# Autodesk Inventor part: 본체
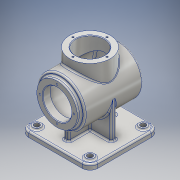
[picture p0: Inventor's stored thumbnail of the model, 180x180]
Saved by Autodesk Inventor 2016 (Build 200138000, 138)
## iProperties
Created: 2015-07
Part Number: 본체
Material: 알루미늄 6061
Document SubType Name: Modeling
Designer: Administrator
Density: 2.7 g/cm^3
Appearance: 알루미늄 - 평지
Mass: 1272.8 g
Surface Area: 1268 cm^2
Volume: 471.408 cm^3
Author: Administrator
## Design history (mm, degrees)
sketch "스케치1"
  geometry: L1 (-65, 65)-(65, 65); L2 (65, 65)-(65, -65); L3 (65, -65)-(-65, -65); L4 (-65, -65)-(-65, 65); 3 further points
  constraints: 8 end point, 2 midpoint, 2 parallel, 2 perpendicular, 1 horizontal, 1 horizontal alignment, 1 vertical alignment
  dimensions: "d0" = 130 distance of L1.start L1.end
extrude "돌출1" new body sketch "스케치1" distance "d1" = 10; taper "d2" = 0 deg
fillet "모깎기1" dims "d3" = 15
sketch "스케치2"
  geometry: C1 r 7.5 at (-50, 50); C2 r 7.5 at (50, 50); C3 r 7.5 at (-50, -50); C4 r 7.5 at (50, -50); A1 r 15 centre (-50, -50) between (-65, -50) and (-50, -65) reference; A2 r 15 centre (-50, 50) between (-50, 65) and (-65, 50) reference; A3 r 15 centre (50, 50) between (65, 50) and (50, 65) reference; A4 r 15 centre (50, -50) between (50, -65) and (65, -50) reference; 5 further points
  constraints: 8 coincident, 4 centre point
  dimensions: "d4" = 15 diameter of C1; "d5" = 15 diameter of C2; "d6" = 15 diameter of C3; "d7" = 15 diameter of C4
extrude "돌출2" join sketch "스케치2" distance "d8" = 3; taper "d9" = 0 deg
sketch "스케치4"
  geometry: C1 r 7.5 at (0, 100) reference; C2 r 7.5 at (0, 0) reference; C3 r 7.5 at (100, 0) reference; C4 r 7.5 at (100, 100) reference; 5 further points
  constraints: 4 coincident
hole "구멍1" sketch "스케치4" at (0, 100), (0, 0), (100, 0), (100, 100) diameter "d10" = 10; stored, may be unused: countersink angle "d14" = 90 deg, drill point angle "d16" = 118 deg; dims "d11" = 6, "d12" = 4, "d13" = 2, "d15" = 8
sketch "스케치6"
  geometry: L1 (-5, 45)-(5, 45); L2 (5, -45)-(-5, -45); L3 (45, 5)-(45, -5); L4 (-45, -5)-(-45, 5); L5 (-5, -45)-(-5, -5); L6 (-5, 5)-(-5, 45); L7 (-45, 5)-(-5, 5); L8 (5, 5)-(45, 5); L9 (5, 45)-(5, 5); L10 (5, -5)-(5, -45); L11 (45, -5)-(5, -5); L12 (-5, -5)-(-45, -5); 3 further points
  constraints: 24 end point, 10 parallel, 6 equal length, 4 perpendicular, 3 horizontal, 2 midpoint, 1 horizontal alignment, 1 vertical alignment
  dimensions: "d17" = 10 distance of L1.start L1.end; "d18" = 90 distance between parallel lines of L2 L1; "d19" = 90 distance between parallel lines of L3 L4; "d20" = 10 distance of L4.start L4.end
extrude "돌출3" join sketch "스케치6" distance "d21" = 68; taper "d22" = 0 deg
sketch "스케치7"
  geometry: C1 r 45 at (0, 78); 1 further point
  constraints: 1 centre point, 1 vertical alignment
  dimensions: "d23" = 90 diameter of C1; "d24" = 78 distance of point (0, 0) C1.centre
extrude "돌출4" join sketch "스케치7" stored distance "d25" = 110; taper "d26" = 0 deg
sketch "스케치9"
  geometry: C1 r 45 at (0, 0) reference; C2 r 38 at (0, 0); 1 further point
  constraints: 1 centre point, 1 coincident
  dimensions: "d27" = 76 diameter of C2
extrude "돌출5" join sketch "스케치9" distance "d28" = 7; taper "d29" = 0 deg
sketch "스케치10"
  geometry: L1 (0, 0)-(0, 140); L2 (0, 140)-(38, 140); L3 (38, 140)-(38, 95); L4 (38, 95)-(0, 95)
  constraints: 8 end point, 2 perpendicular, 1 horizontal, 1 point on line
  dimensions: "d31" = 140 distance of L1.start L1.end; "d32" = 76 diameter of L3 L1; "d33" = 45 distance of L2.end L3.end
revolve "회전1" sketch "스케치10" stored, may be unused: angle "d34" = 90 deg
sketch "스케치11"
  geometry: L1 (-62, 116)-(-62, 40) reference; L2 (-62, 78)-(55, 78); L3 (55, 33)-(55, 123) reference; L4 (-62, 105)-(-48, 105); L5 (-48, 105)-(-48, 118); L6 (-48, 118)-(48, 118); L7 (48, 118)-(48, 78); L8 (-62, 105)-(-62, 78); 1 further point
  constraints: 12 end point, 4 perpendicular, 2 midpoint, 2 point on line, 1 horizontal
  dimensions: "d35" = 14 distance of L4.start L4.end; "d36" = 54 diameter of L4 L2; "d37" = 80 diameter of L6 L2; "d38" = 96 distance of L5.end L6.end
revolve "회전2" sketch "스케치11" stored, may be unused: angle "d39" = 90 deg
sketch "스케치12"
  geometry: 2 further points
  constraints: 1 coincident
hole "구멍2" sketch "스케치12" at (0, 0) diameter "d40" = 54; stored, may be unused: countersink angle "d44" = 90 deg, drill point angle "d46" = 0 deg; dims "d41" = 6, "d42" = 4, "d43" = 2, "d45" = 8
sketch "스케치13"
  geometry: C1 r 27 at (0, 0) reference; A1 r 32 centre (0, 0) between (0, 32) and (-32, 0); 3 further points
  constraints: 4 point on circle, 2 horizontal alignment, 2 vertical alignment, 1 centre point, 1 coincident
  dimensions: "d47" = 64 diameter of A1
hole "구멍3" sketch "스케치13" at (0, 32), (-32, 0), (0, -32), (32, 0) diameter "d48" = 3.242; stored, may be unused: countersink angle "d52" = 90 deg, drill point angle "d54" = 118 deg; dims "d49" = 8, "d50" = 4, "d51" = 2, "d53" = 10
sketch "스케치14"
  geometry: A1 r 32 centre (0, 0) between (0, 32) and (-32, 0); 3 further points
  constraints: 4 point on circle, 2 horizontal alignment, 2 vertical alignment, 1 centre point, 1 coincident
  dimensions: "d55" = 64 diameter of A1
hole "구멍4" sketch "스케치14" at (0, 32), (-32, 0), (0, -32), (32, 0) diameter "d56" = 3.242; stored, may be unused: countersink angle "d60" = 90 deg, drill point angle "d62" = 118 deg; dims "d57" = 8, "d58" = 4, "d59" = 2, "d61" = 10
fillet "모깎기2" dims "d63" = 3
fillet "모깎기3" dims "d64" = 3
sketch "스케치15"
  geometry: 3 further points
  constraints: 1 coincident, 1 other
feature "엠보싱1" sketch "스케치15" dims "d0" = 130, "d65" = 0.5, "d66" = 0
fillet "모깎기4" dims "d67" = 3
chamfer "모따기1" distance "d68" = 1; stored, may be unused: second distance "d69" = 2, angle "d70" = 45 deg
node "솔리드1"
node "투영된 루프1"
node "투영된 루프2"
node "투영된 루프3"
